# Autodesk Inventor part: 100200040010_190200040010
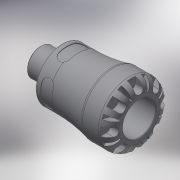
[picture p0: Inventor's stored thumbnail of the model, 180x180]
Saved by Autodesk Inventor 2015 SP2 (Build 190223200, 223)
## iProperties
Created: 2016-12
Part Number: 100200040010_190200040010
Material: Generic
Description: PLASSON MALE ADAPTOR 40X1" SERIES 1
Document SubType Name: Modeling
Designer: KIM
Mass: 447.839 g
Surface Area: 722.341 cm^2
Volume: 447.839 cm^3
Density: 1 g/cm^3
Appearance: Default
Author: KIM
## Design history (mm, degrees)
derived "1002.ipt"
feature "Solid1::1002.ipt"
tag "TaggingFeature1"
body "Solid1"
other parameters: "d0" = 104, "d1" = 30.66, "d6" = 73, "d8" = 59.5, "d13" = 8, "d14" = 8, "d15" = 0, "d17" = 360 deg, "d19" = 8 deg, "d20" = 0.8, "d21" = 0.8, "d22" = 8 deg, "d24" = 0, "d26" = 360 deg, "d32" = 0.925, "d33" = 7, "d34" = 33.249, "d35" = 8, "d38" = 19, "d39" = 0.99747, "d42" = 14, "d43" = 9.2, "d45" = 15.68, "d46" = 0, "d59" = 360 deg, "d61" = 11.9, "d62" = 0.8, "d64" = 0, "d65" = 0.7, "H_" = 104, "l_" = 73, "R_" = 33.249, "l_2" = 19, "d9" = 10
